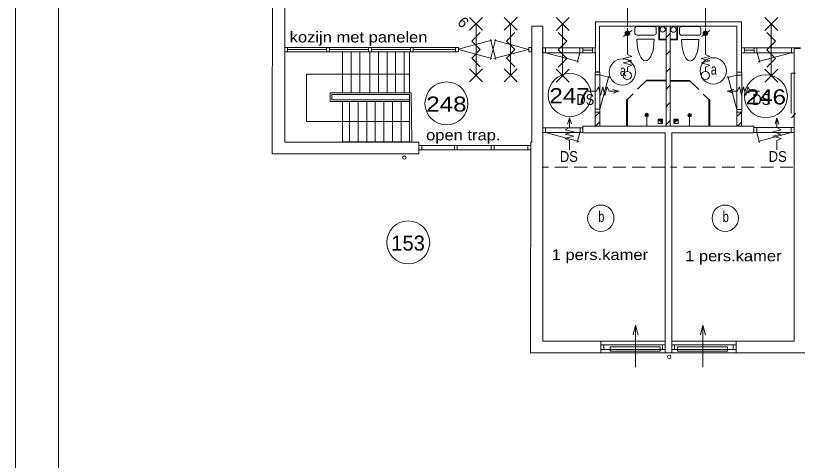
# Model space of a CAD drawing. Extents: x 295824 to 414724, y 24924 to 109024.
# Drawn here: x 295824 to 314015, y 85056 to 95396 of the extents above; entities that cross this region are included whole.
import ezdxf
from ezdxf.enums import TextEntityAlignment as Align

# ---------------------------------------------------------------- set-up
doc = ezdxf.new("R2010")
doc.units = 0
doc.header["$LTSCALE"] = 100
doc.linetypes.add('MEDIUM_DASHED', pattern=[4.5, 3, -1.5])
for name, color, linetype, lineweight in [('1', 7, 'Continuous', 13), ('16', 7, 'Continuous', 13), ('24', 7, 'Continuous', 13), ('61', 7, 'Continuous', 13)]:
    doc.layers.add(name, color=color, linetype=linetype, lineweight=lineweight)

msp = doc.modelspace()

# ---------------------------------------------------------------- hatches: boundary and pattern name
at = {"layer": '24'}
for points in [[(310114.2, 94981.2, 1), (310005.6, 94981.2, 1)], [(311929.8, 94981.2, 1), (311821.2, 94981.2, 1)]]:
    msp.add_hatch(color=256, dxfattribs=at).paths.add_polyline_path(points)
at = {"layer": '61'}
for points in [[(310777.4, 92991.3), (310877.4, 92891.3), (310877.4, 92991.3)], [(311239.9, 92985.9), (311139.9, 92885.9), (311139.9, 92985.9)]]:
    msp.add_hatch(color=256, dxfattribs=at).paths.add_polyline_path(points)

# ---------------------------------------------------------------- linework, layer by layer
at = {"layer": '1'}
for p, q in [((295823.6, 109023.8), (295823.6, 24923.8)), ((310059.9, 95135.8), (310059.9, 96018.7)), ((311875.5, 95130.8), (311875.5, 96018.7))]:
    msp.add_line(p, q, dxfattribs=at)
msp.add_lwpolyline([(304995.6, 108023.8), (296823.6, 108023.8), (296823.6, 25923.8), (304995.6, 25923.8)], dxfattribs=at)
at = {"layer": '16'}
for p, q in [((309487.2, 93739.9), (309437.2, 93539.9)), ((312764.7, 93739.9), (312814.7, 93539.9)), ((308610.8, 92641.7), (308810.8, 92591.7)), ((313641.1, 92641.7), (313441.1, 92591.7))]:
    msp.add_line(p, q, dxfattribs=at)
at = {"layer": '24'}
for p, q in [((309968.3, 94910.4), (310159.9, 95052.1)), ((310059.9, 94545.8), (310059.9, 95106.6)), ((311783.9, 94910.4), (311975.4, 95052.1)), ((311875.5, 94545.8), (311875.5, 95108.1)), ((309862.6, 93636.5), (309718.4, 93681.5)), ((309726.8, 93594.1), (309862.6, 93636.5)), ((312389.2, 93636.5), (312533.4, 93681.5)), ((312525.1, 93594.1), (312389.2, 93636.5)), ((308714.2, 93017.1), (308669.1, 92872.9)), ((308756.6, 92881.3), (308714.2, 93017.1)), ((313495.3, 92881.3), (313537.7, 93017.1)), ((313537.7, 93017.1), (313582.7, 92872.9)), ((310251.5, 88195.7), (310191.9, 87973.2)), ((311817.2, 88195.7), (311757.6, 87973.2))]:
    msp.add_line(p, q, dxfattribs=at)
for points in [[(310059.9, 94095.8), (310059.9, 94195.8), (310159.9, 94245.8), (309959.9, 94295.8), (310159.9, 94345.8), (309959.9, 94395.8), (310159.9, 94445.8), (310059.9, 94495.8), (310059.9, 94545.8)], [(311875.5, 94095.8), (311875.5, 94195.8), (311975.5, 94245.8), (311775.5, 94295.8), (311975.5, 94345.8), (311775.5, 94395.8), (311975.5, 94445.8), (311875.5, 94495.8), (311875.5, 94545.8)], [(309437.2, 93539.9), (309387.2, 93739.9), (309337.2, 93639.9), (309118.5, 93639.9)], [(309868.4, 93639.9), (309637.2, 93639.9), (309587.2, 93739.9), (309537.2, 93539.9), (309487.2, 93739.9)], [(312383.4, 93639.9), (312614.7, 93639.9), (312664.7, 93739.9), (312714.7, 93539.9), (312764.7, 93739.9)], [(312814.7, 93539.9), (312864.7, 93739.9), (312914.7, 93639.9), (313133.4, 93639.9)], [(308710.8, 93023), (308710.8, 92791.7), (308610.8, 92741.7), (308810.8, 92691.7), (308610.8, 92641.7)], [(313541.1, 93023), (313541.1, 92791.7), (313641.1, 92741.7), (313441.1, 92691.7), (313641.1, 92641.7)], [(308810.8, 92591.7), (308610.8, 92541.7), (308710.8, 92491.7), (308710.8, 92273)], [(313441.1, 92591.7), (313641.1, 92541.7), (313541.1, 92491.7), (313541.1, 92273)], [(310251.5, 87220.7), (310251.5, 88195.7), (310313.2, 87965.5)], [(311817.2, 87220.7), (311817.2, 88195.7), (311878.8, 87965.5)]]:
    msp.add_lwpolyline(points, dxfattribs=at)
for points in [[(309660.2, 87691.5), (310826.1, 87691.5), (310826.1, 87591.5), (309660.2, 87591.5)], [(311225.9, 87691.5), (312391.8, 87691.5), (312391.8, 87591.5), (311225.9, 87591.5)]]:
    msp.add_lwpolyline(points, close=True, dxfattribs=at)
for centre, radius in [((310059.9, 94981.2), 54.3), ((311875.5, 94981.2), 54.3), ((310059.9, 94004.2), 95), ((311875.5, 94004.2), 95)]:
    msp.add_circle(centre, radius, dxfattribs=at)
at = {"layer": '61'}
for p, q in [((302090.1, 94558.1), (302090.1, 97322)), ((306687.3, 95355.9), (306387.3, 95055.9)), ((306387.3, 95355.9), (306687.3, 95055.9)), ((307493.3, 95355.9), (307193.3, 95055.9)), ((307193.3, 95355.9), (307493.3, 95055.9)), ((308402.5, 95051.1), (308702.5, 95351.1)), ((308702.5, 95051.1), (308402.5, 95351.1)), ((313258.4, 95051.1), (313558.4, 95351.1)), ((313558.4, 95051.1), (313258.4, 95351.1)), ((306537.3, 94005.9), (306537.3, 95205.9)), ((307343.3, 94005.9), (307343.3, 95205.9)), ((308090.1, 95148.4), (308090.1, 87823.4)), ((308552.5, 95201.1), (308552.5, 94001.1)), ((309409.2, 94086.3), (309409.2, 95148.4)), ((310282.4, 95145.4), (310682.4, 95145.4)), ((310809.2, 94848.4), (310809.2, 95148.4)), ((310959.2, 92823.4), (310959.2, 95148.4)), ((311055.5, 92823.4), (311055.5, 95148.4)), ((311209.3, 95147.9), (311209.3, 94847.9)), ((313408.4, 95201.1), (313408.4, 94001.1)), ((310232.4, 94995.4), (310232.4, 95095.4)), ((310732.4, 95095.4), (310732.4, 94995.4)), ((311054.9, 94982.4), (310959.2, 94886.7)), ((311271.8, 94990.5), (311271.8, 95090.5)), ((311321.8, 95140.5), (311721.8, 95140.5)), ((311771.8, 95090.5), (311771.8, 94990.5)), ((306127.9, 94617), (306903.9, 94824.9)), ((306994, 94838.6), (306870.9, 94379.1)), ((306998.8, 94372.3), (306873, 94842)), ((306968.5, 94823.2), (307758.5, 94611.5)), ((310682.4, 94945.4), (310282.4, 94945.4)), ((310282.4, 94845.4), (310682.4, 94845.4)), ((310959.2, 94848.4), (310809.2, 94848.4)), ((311209.3, 94847.9), (311059.3, 94847.9)), ((311721.8, 94940.5), (311321.8, 94940.5)), ((311321.8, 94840.5), (311721.8, 94840.5)), ((302090.5, 94658.1), (306126.4, 94658.1)), ((302152.3, 94557.9), (302152.3, 94657.9)), ((302153.3, 94611.3), (303061.3, 94611.3)), ((303060.3, 94557.9), (303060.3, 94657.9)), ((303127.3, 94557.9), (303127.3, 94657.9)), ((303127.6, 94611.3), (304035.6, 94611.3)), ((304035.3, 94557.9), (304035.3, 94657.9)), ((304101.9, 94611.3), (305009.9, 94611.3)), ((304102.3, 94557.9), (304102.3, 94657.9)), ((305010.3, 94557.9), (305010.3, 94657.9)), ((305077.3, 94557.9), (305077.3, 94657.9)), ((305078.6, 94611.3), (306052.9, 94611.3)), ((306055.9, 94557.9), (306055.9, 94657.9)), ((306126.4, 94558.1), (306126.4, 94658.1)), ((306127.9, 94606.3), (306906.8, 94397.6)), ((306955.3, 94396.3), (307756.8, 94611)), ((307764.7, 94558.1), (307764.7, 94658.1)), ((307764.7, 94658.1), (307831.7, 94658.1)), ((307831.7, 94558.1), (307831.7, 94658.1)), ((307832.8, 94655.7), (307832.8, 92454.5)), ((308153, 94648.3), (308153, 94534.3)), ((308953, 94648.3), (308953, 94534.3)), ((309020, 94648.3), (309020, 94534.3)), ((309246, 94648.3), (309246, 94534.3)), ((312714.4, 94084.9), (312714.4, 94650.7)), ((312782.6, 94648.3), (312782.6, 94534.3)), ((313008.6, 94648.3), (313008.6, 94534.3)), ((313075.6, 94648.3), (313075.6, 94534.3)), ((313875.6, 94648.3), (313875.6, 94534.3)), ((313944.8, 94648.3), (314086, 94648.3)), ((313944.8, 94633.3), (314086, 94633.3)), ((302090.1, 92454.5), (302090.1, 94554.5)), ((302090.5, 94558.1), (306126.4, 94558.1)), ((303433.4, 93599.7), (303433.4, 94552)), ((303633.4, 93602.1), (303633.4, 94552)), ((303833.4, 93609.5), (303833.4, 94552)), ((304065.8, 93599.7), (304065.8, 94546.5)), ((304265.8, 93599.7), (304265.8, 94552.7)), ((304465.8, 93599.7), (304465.8, 94552.7)), ((304665.8, 93599.7), (304665.8, 94552.7)), ((304865.8, 93599.7), (304865.8, 94552.7)), ((307764.7, 94558.1), (307831.7, 94558.1)), ((308152.2, 94533.7), (308925, 94326.6)), ((308950.6, 94533.1), (308889.9, 94306.2)), ((309246, 94594.2), (309020, 94594.2)), ((309314.4, 94086.3), (309314.4, 94548.4)), ((311054.9, 94581.5), (310959.2, 94485.8)), ((312782.6, 94594.2), (313008.6, 94594.2)), ((313078, 94533.1), (313138.7, 94306.2)), ((313876.4, 94533.7), (313103.6, 94326.6)), ((313940.1, 94548.4), (313940.1, 87823.4)), ((306687.3, 94155.9), (306387.3, 93855.9)), ((306387.3, 94155.9), (306687.3, 93855.9)), ((307493.3, 94155.9), (307193.3, 93855.9)), ((307193.3, 94155.9), (307493.3, 93855.9)), ((308402.5, 93851.1), (308702.5, 94151.1)), ((308702.5, 93851.1), (308402.5, 94151.1)), ((309306.9, 93151.5), (309306.9, 94085.5)), ((309409.2, 94086.3), (309314.4, 94086.3)), ((311054.9, 94178.2), (310959.2, 94082.4)), ((312714.4, 94084.9), (312609.2, 94084.9)), ((312720.4, 93148.9), (312720.4, 94081.3)), ((313258.4, 93851.1), (313558.4, 94151.1)), ((313558.4, 93851.1), (313258.4, 94151.1)), ((313872.9, 93123.7), (313872.9, 94057.7)), ((313975.1, 94058.5), (313880.4, 94058.5)), ((303983.1, 94033.5), (304996.9, 94033.5)), ((309306.9, 94018.5), (309420.9, 94018.5)), ((309419, 93217.8), (309626, 93990.5)), ((309419.6, 94016.2), (309646.5, 93955.4)), ((310960.3, 93897), (310510.8, 93897)), ((310510.8, 93897), (310510.8, 93879)), ((310960, 93879), (310510.8, 93879)), ((311057, 93891.6), (311506.5, 93891.6)), ((311057.3, 93873.6), (311506.5, 93873.6)), ((311506.5, 93891.6), (311506.5, 93873.6)), ((312602.6, 94011.9), (312375.7, 93951.2)), ((312603.2, 93213.5), (312396.2, 93986.3)), ((312720.4, 94014.3), (312606.4, 94014.3)), ((311054.9, 93782.2), (310959.2, 93686.4)), ((303433.4, 93599.7), (303140.1, 93599.7)), ((303140.1, 93599.7), (303140.1, 93397.7)), ((303180.1, 93559.7), (304991.2, 93559.7)), ((303180.1, 93559.7), (303180.1, 93437.7)), ((303865.8, 93599.7), (305030.8, 93599.7)), ((304991.2, 93559.7), (304992.8, 93397.7)), ((305030.8, 93599.7), (305042.2, 92457.9)), ((303433.4, 93397.7), (303140.1, 93397.7)), ((303180.1, 93437.7), (304992.8, 93437.7)), ((303592.8, 92459.8), (303592.8, 93397.7)), ((303792.8, 92459.8), (303792.8, 93397.7)), ((303992.8, 92459.8), (303992.8, 93397.7)), ((304192.8, 92459.8), (304192.8, 93397.7)), ((304392.8, 92459.8), (304392.8, 93397.7)), ((304592.8, 92459.8), (304592.8, 93397.7)), ((304792.8, 92459.8), (304792.8, 93397.7)), ((304992.8, 92459.8), (304992.8, 93397.7)), ((310059.9, 92829), (310059.9, 93449.5)), ((311054.9, 93377.6), (310959.2, 93281.8)), ((311957.4, 92823.6), (311957.4, 93444.1)), ((309420.3, 93151.5), (309306.3, 93151.5)), ((309306.9, 93218.5), (309420.9, 93218.5)), ((309409.3, 93146.8), (309309.6, 93047.1)), ((309419.6, 93148), (309309.7, 93148)), ((309309.7, 93148), (309309.7, 92823.9)), ((309419.6, 93148), (309419.6, 92823.9)), ((312720.4, 93214.3), (312606.4, 93214.3)), ((312707.8, 93146.8), (312608.1, 93047.1)), ((312718.6, 93148), (312608.6, 93148)), ((312608.6, 93148), (312608.6, 92823.9)), ((312718.6, 93148), (312718.6, 92823.9)), ((310559.8, 93085.5), (310459.8, 93085.5)), ((310545.2, 93050.1), (310474.4, 93120.8)), ((310545.2, 93120.8), (310474.4, 93050.1)), ((310509.8, 93035.5), (310509.8, 93135.5)), ((310509.8, 93035.5), (310509.8, 92835.5)), ((311054.9, 92959.5), (310959.2, 92863.7)), ((311457.5, 93080.1), (311557.5, 93080.1)), ((311472.1, 93044.8), (311542.9, 93115.5)), ((311472.1, 93115.5), (311542.9, 93044.8)), ((311507.5, 93030.1), (311507.5, 93130.1)), ((311507.5, 93030.1), (311507.5, 92830.1)), ((313975.2, 93118.9), (313875.5, 93019.2)), ((308157.6, 92790.9), (308157.6, 92676.9)), ((308957.6, 92790.9), (308957.6, 92676.9)), ((309024.6, 92790.9), (309024.6, 92676.9)), ((309419.6, 92823.9), (309309.7, 92823.9)), ((309417.9, 92924.2), (309318.2, 92824.5)), ((312718.6, 92823.9), (312608.6, 92823.9)), ((312720.1, 92924.2), (312620.4, 92824.5)), ((313005.2, 92791.9), (313005.2, 92677.9)), ((313072.2, 92791.9), (313072.2, 92677.9)), ((313872.2, 92791.9), (313872.2, 92677.9)), ((308156.8, 92676.2), (308929.5, 92469.2)), ((308955.2, 92675.6), (308894.4, 92448.8)), ((310940.1, 87553.8), (310940.1, 92673.4)), ((311090.1, 87553.8), (311090.1, 92673.4)), ((313074.6, 92676.7), (313135.4, 92449.8)), ((313873, 92677.3), (313100.3, 92470.3)), ((305206.2, 92454.5), (302090.1, 92454.5)), ((305206.2, 92184.5), (305206.2, 92454.5)), ((307806, 87553.4), (307811.7, 92454.5)), ((307832.8, 92454.5), (307811.7, 92454.5)), ((305206.6, 92272.5), (305206.6, 92373.4)), ((305206.6, 92373.4), (307811.6, 92373.4)), ((305206.6, 92272.5), (307810.6, 92272.5)), ((305273.6, 92273.4), (305273.6, 92373.4)), ((306035.3, 92273.4), (306035.3, 92373.4)), ((306102.3, 92273.4), (306102.3, 92373.4)), ((306889.3, 92273.4), (306889.3, 92373.4)), ((306956.6, 92272.5), (306956.6, 92373.4)), ((307740.6, 92373.4), (307807.6, 92373.4)), ((307743.6, 92272.5), (307743.6, 92373.4)), ((307810.6, 92272.5), (307810.6, 92373.4)), ((305206.2, 92184.5), (301796.6, 92184.5)), ((308090.1, 87823.4), (310940.1, 87823.4)), ((309441.5, 87552.2), (309441.5, 87822.2)), ((309508.3, 87630.5), (309508.3, 87744.3)), ((310873.3, 87629.9), (310873.3, 87743.9)), ((313940.1, 87823.4), (311090.1, 87823.4)), ((311156.8, 87630.8), (311156.8, 87744.8)), ((312521.1, 87630.5), (312521.1, 87744.2)), ((312589.8, 87552.2), (312589.8, 87821.5)), ((326233, 87553.4), (307806, 87553.4))]:
    msp.add_line(p, q, dxfattribs=at)
at = {"layer": '61', "linetype": 'MEDIUM_DASHED'}
for p, q in [((310508.8, 93896.5), (310061.9, 93449.6)), ((311508.5, 93891.2), (311955.4, 93444.3)), ((310922.5, 91870), (308075.5, 91870)), ((313911.6, 91870), (311064.6, 91870))]:
    msp.add_line(p, q, dxfattribs=at)
at = {"layer": '61'}
for points in [[(301796.6, 92184.5), (301820.1, 104417.6), (332210.1, 104417.6)], [(308090.1, 95148.4), (307832.8, 95148.4), (307832.8, 94654.5)], [(312714.4, 94648.4), (312714.4, 95248.4), (309314.4, 95248.4), (309314.4, 94648.4)], [(312609.2, 94084.9), (312609.2, 95148.4), (309409.2, 95148.4)], [(310959.2, 94833.4), (310794.2, 94833.4), (310794.2, 95148.4)], [(311224.3, 95147.9), (311224.3, 94832.9), (311059.3, 94832.9)], [(306637.3, 94205.9), (306437.3, 94405.9), (306637.3, 94605.9), (306437.3, 94805.9), (306637.3, 95005.9)], [(307443.3, 94205.9), (307243.3, 94405.9), (307443.3, 94605.9), (307243.3, 94805.9), (307443.3, 95005.9)], [(308452.5, 95001.1), (308652.5, 94801.1), (308452.5, 94601.1), (308652.5, 94401.1), (308452.5, 94201.1)], [(313308.4, 95001.1), (313508.4, 94801.1), (313308.4, 94601.1), (313508.4, 94401.1), (313308.4, 94201.1)], [(304990.8, 93599.7), (303433.4, 93599.7), (303433.4, 94552), (304122.8, 94552)], [(304990.8, 93599.7), (304990.8, 94552.7), (304123.5, 94552.7)], [(304992.8, 92935.9), (302596, 92935.9), (302596, 94032.5), (303992.5, 94032.5)], [(310041.9, 92829), (310041.9, 93449.5), (310059.9, 93449.5)], [(311975.4, 92823.6), (311975.4, 93444.1), (311957.4, 93444.1)], [(310877.4, 92891.3), (310877.4, 92991.3), (310777.4, 92991.3)], [(311139.9, 92885.9), (311139.9, 92985.9), (311239.9, 92985.9)], [(308090.6, 92790.9), (308090.6, 92676.9), (309024.6, 92676.9)], [(309024.6, 92790.9), (308090.6, 92790.9), (308090.6, 92676.9)], [(311089.4, 92673.4), (313004.4, 92673.4), (313004.4, 92823.4), (309025.1, 92823.4)], [(310939.4, 92673.4), (309025.1, 92673.4), (309025.1, 92823.4)], [(313939.2, 92791.9), (313939.2, 92677.9), (313005.2, 92677.9)], [(313005.2, 92791.9), (313939.2, 92791.9), (313939.2, 92677.9)]]:
    msp.add_lwpolyline(points, dxfattribs=at)
for points in [[(309313, 94648.3), (309313, 94534.3), (308086, 94534.3), (308086, 94648.3)], [(309313, 94648.3), (309313, 94534.3), (308086, 94534.3), (308086, 94648.3)], [(313942.6, 94648.3), (313942.6, 94534.3), (312716.2, 94534.3), (312716.2, 94648.3)], [(313942.6, 94648.3), (313942.6, 94534.3), (312716.2, 94534.3), (312716.2, 94648.3)], [(309306.9, 93151.5), (309306.9, 94085.5), (309420.9, 94085.5), (309420.9, 93151.5)], [(312720.4, 94082.2), (312606.4, 94082.2), (312606.4, 93148.2), (312720.4, 93148.2)], [(304992.8, 92459.8), (303433.4, 92459.8), (303433.4, 93397.7), (304992.8, 93397.7)], [(310877.4, 92891.3), (310777.4, 92891.3), (310777.4, 92991.3)], [(310777.4, 92991.3), (310877.4, 92891.3), (310877.4, 92991.3)], [(311139.9, 92885.9), (311239.9, 92885.9), (311239.9, 92985.9)], [(311239.9, 92985.9), (311139.9, 92885.9), (311139.9, 92985.9)], [(309441.5, 87630.3), (309441.5, 87744.3), (310940.1, 87744.3), (310940.1, 87630.3)], [(311090.5, 87630.5), (311090.5, 87744.5), (312589.8, 87744.5), (312589.8, 87630.5)]]:
    msp.add_lwpolyline(points, close=True, dxfattribs=at)
for centre, radius in [((310881.7, 95075.9), 62.5), ((311131.7, 95070.4), 62.5), ((312058.4, 94112.4), 306.3), ((309942.5, 94084.5), 306.3), ((308717.2, 93549.6), 500), ((313283.2, 93521.8), 500), ((305849.6, 93354.6), 500), ((304869.5, 92095.7), 40), ((309441.3, 90685.4), 306.3), ((312336.8, 90685.4), 306.3), ((304958.7, 90122.7), 500), ((311034.3, 87463.3), 40)]:
    msp.add_circle(centre, radius, dxfattribs=at)
for centre, start, end in [((310282.4, 95095.4), 90, 180), ((310682.4, 95095.4), 0, 90), ((310282.4, 94995.4), 180, 270), ((310682.4, 94995.4), 270, 0), ((311321.8, 95090.5), 90, 180), ((311321.8, 94990.5), 180, 270), ((311721.8, 95090.5), 0, 90), ((311721.8, 94990.5), 270, 0)]:
    msp.add_arc(centre, 50, start, end, dxfattribs=at)
for centre in [(310482.4, 94845.4), (311521.8, 94840.5)]:
    msp.add_ellipse(centre, major_axis=(0, -500), ratio=0.4, start_param=4.712389, end_param=7.8539816, dxfattribs=at)

# ---------------------------------------------------------------- texts
at = {"layer": '24', "width": 0.9}
for p in [(308872, 93320.9), (312966.5, 93320.9), (308488.9, 91995.9), (313349.5, 91995.9)]:
    msp.add_text('DS', height=250, dxfattribs=at).set_placement(p)
at = {"layer": '61'}
msp.add_text('6', height=250, rotation=315, dxfattribs=at).set_placement((306086.5, 95220))
for s, width, p in [('kozijn met panelen', 1.15, (302200.9, 94772.8)), ('a', 0.75, (309884.5, 93995.3)), ('a', 0.75, (312000.4, 94023.2)), ('open trap.', 1.15, (305375.1, 92495.4)), ('b', 0.75, (309383.3, 90596.2)), ('b', 0.75, (312278.8, 90596.2)), ('1 pers.kamer', 1.15, (308297.8, 89713.2)), ('1 pers.kamer', 1.15, (311404.3, 89683.7))]:
    msp.add_text(s, height=250, dxfattribs=dict(at, width=width)).set_placement(p)
at = {"layer": '61', "width": 1.2}
for s, p in [('247', (308714.3, 93359.8)), ('246', (313281.6, 93331.9)), ('248', (305848.1, 93164.7))]:
    msp.add_text(s, height=350, dxfattribs=at).set_placement(p, align=Align.CENTER)
at = {"layer": '61'}
msp.add_text('153', height=350, dxfattribs=at).set_placement((304955.8, 89932.8), align=Align.CENTER)

doc.saveas('drawing.dxf')
